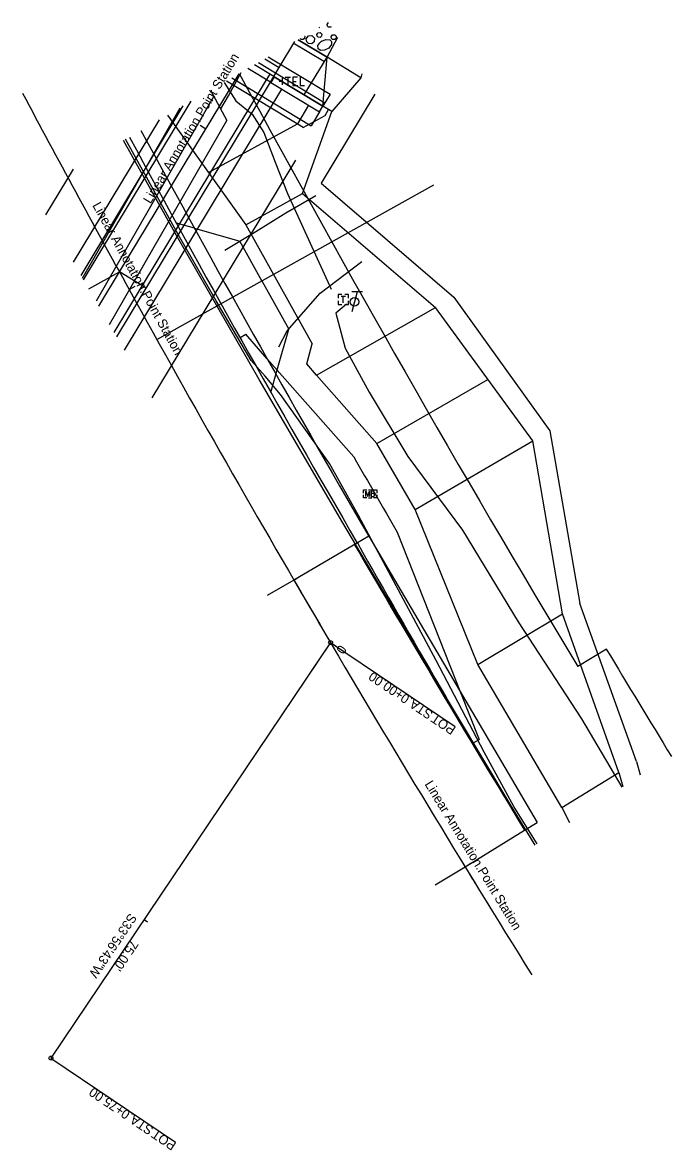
# Model space of a CAD drawing. Extents: x 2231639 to 2237084, y 681731 to 684172.
# Drawn here: x 2231639.3 to 2231736.5, y 683534.5 to 683703.4 of the extents above; entities that cross this region are included whole.
import ezdxf

# ---------------------------------------------------------------- set-up
doc = ezdxf.new("R2010")
doc.units = 0
for name, color, linetype in [('DR_P_Erosion_Control', 7, 'Continuous'), ('DR_P_Paved_Gutter', 7, 'Continuous'), ('DR_X_Storm_Sewer', 7, 'Continuous'), ('DT_P_Slope_Break_Line', 7, 'Continuous'), ('GE_P_Alignment', 7, 'Continuous'), ('GE_P_Alignment_100_Bearings', 7, 'Continuous'), ('GE_P_Alignment_100_Cardinal_Points', 7, 'Continuous'), ('GE_P_Alignment_100_Distances', 7, 'Continuous'), ('GE_P_Alignment_100_Stations', 7, 'Continuous'), ('GE_X_Alignment', 7, 'Continuous'), ('GE_X_Alignment_100_Stations', 7, 'Continuous'), ('HY_P_Water_Edge', 7, 'Continuous'), ('HY_X_Water_Edge', 7, 'Continuous'), ('PV_P_Drive', 7, 'Continuous'), ('PV_P_Field_Drive', 7, 'Continuous'), ('PV_X_Driveway', 7, 'Continuous'), ('PV_X_EOP', 7, 'Continuous'), ('PV_X_Shoulder_Aggregate', 7, 'Continuous'), ('RD_X_Cells', 7, 'Continuous'), ('RW_P_Const_Limits', 7, 'Continuous'), ('RW_X_Esmt_SH', 7, 'Continuous'), ('SH_Border', 7, 'Continuous'), ('SH_Cut_Line', 7, 'Continuous'), ('SH_Data', 7, 'Continuous'), ('SH_Masking', 7, 'Continuous'), ('SH_Named_Boundary', 7, 'Continuous'), ('UT_X_Telecom', 7, 'Continuous'), ('UT_X_Telecom_Cells', 7, 'Continuous')]:
    doc.layers.add(name, color=color, linetype=linetype)

msp = doc.modelspace()

# ---------------------------------------------------------------- linework, layer by layer
at = {"layer": 'DR_P_Erosion_Control'}
for p, q in [((2231684.92, 683703.08), (2231685.12, 683703.37)), ((2231684.91, 683698.17), (2231686.55, 683701.18))]:
    msp.add_line(p, q, dxfattribs=at)
for points in [[(2231683.37, 683701.57), (2231683.57, 683701.85), (2231683.9, 683701.87), (2231684.12, 683701.64), (2231684.09, 683701.31), (2231683.89, 683701.15), (2231683.57, 683701.17), (2231683.42, 683701.32), (2231683.37, 683701.57)], [(2231683.77, 683702.64), (2231683.7, 683702.58), (2231683.67, 683702.59)], [(2231685.53, 683702.74), (2231685.44, 683702.67), (2231685.12, 683702.69), (2231684.97, 683702.84), (2231684.92, 683703.08)], [(2231685.54, 683701.25), (2231685.74, 683701.53), (2231686.07, 683701.55), (2231686.29, 683701.32), (2231686.26, 683701), (2231686.06, 683700.83), (2231685.74, 683700.85), (2231685.59, 683701), (2231685.54, 683701.25)], [(2231681.53, 683701.35), (2231681.57, 683701.31), (2231681.54, 683700.98), (2231681.34, 683700.82), (2231681.02, 683700.84), (2231680.88, 683700.98)], [(2231681.78, 683700.91), (2231682.11, 683701.38), (2231682.65, 683701.41), (2231683.02, 683701.03), (2231682.97, 683700.49), (2231682.64, 683700.21), (2231682.11, 683700.25), (2231681.86, 683700.49), (2231681.78, 683700.91)], [(2231684.12, 683700.6), (2231684.75, 683700.85), (2231685.33, 683700.8), (2231685.6, 683700.54), (2231685.59, 683700.07), (2231685.17, 683699.54), (2231684.53, 683699.22), (2231683.92, 683699.21), (2231683.58, 683699.45), (2231683.55, 683699.93), (2231683.83, 683700.36), (2231684.14, 683700.62)]]:
    msp.add_lwpolyline(points, dxfattribs=at)
at = {"layer": 'DR_P_Paved_Gutter'}
for p, q in [((2231677.76, 683696.65), (2231680.1, 683700.52)), ((2231680.56, 683700.79), (2231684.91, 683698.17)), ((2231681.5, 683692.53), (2231684.91, 683698.17))]:
    msp.add_line(p, q, dxfattribs=at)
at = {"layer": 'DR_X_Storm_Sewer'}
for p, q in [((2231654.55, 683654.35), (2231678.13, 683693.4)), ((2231667.44, 683693.23), (2231669.89, 683688.72)), ((2231667.93, 683692.34), (2231650.31, 683661.64)), ((2231648.27, 683665.13), (2231662.91, 683690.62)), ((2231646.9, 683667.49), (2231659.79, 683688.82)), ((2231652.34, 683658.15), (2231669.89, 683688.72)), ((2231642.8, 683674.57), (2231646.93, 683681.41)), ((2231658.72, 683647.17), (2231680.24, 683682.79))]:
    msp.add_line(p, q, dxfattribs=at)
at = {"layer": 'DT_P_Slope_Break_Line'}
for p, q in [((2231684.91, 683698.17), (2231680.56, 683700.79)), ((2231684.28, 683690.85), (2231684.91, 683698.17)), ((2231689.95, 683695.12), (2231684.91, 683698.17)), ((2231684.28, 683690.85), (2231677.01, 683695.25)), ((2231689.95, 683695.12), (2231685.63, 683690.04)), ((2231690.12, 683695.67), (2231689.95, 683695.12)), ((2231682.15, 683690.98), (2231680.46, 683688.19)), ((2231681.25, 683677.78), (2231685.63, 683690.04)), ((2231685.63, 683690.04), (2231684.28, 683690.85)), ((2231661.02, 683689.53), (2231672.76, 683673.08)), ((2231667.17, 683680.91), (2231680.46, 683688.19)), ((2231672.76, 683673.08), (2231681.25, 683677.78)), ((2231681.25, 683677.78), (2231701.15, 683660.71)), ((2231672.76, 683673.08), (2231682.7, 683655.28)), ((2231683.35, 683650.6), (2231701.15, 683660.71)), ((2231715.72, 683640.76), (2231701.15, 683660.71)), ((2231681.86, 683652.29), (2231682.7, 683655.28)), ((2231683.35, 683650.6), (2231681.86, 683652.29)), ((2231692.39, 683640.33), (2231683.35, 683650.6)), ((2231692.39, 683640.33), (2231709, 683649.95)), ((2231698.09, 683630.49), (2231715.72, 683640.76)), ((2231720.2, 683614.85), (2231715.72, 683640.76)), ((2231698.09, 683630.49), (2231692.39, 683640.33)), ((2231707.51, 683607.27), (2231698.09, 683630.49)), ((2231707.51, 683607.27), (2231720.2, 683614.85)), ((2231728.61, 683591.1), (2231720.2, 683614.85)), ((2231720.08, 683585.88), (2231707.51, 683607.27)), ((2231720.08, 683585.88), (2231728.61, 683591.1)), ((2231728.61, 683591.1), (2231729.21, 683588.99)), ((2231720.08, 683585.88), (2231721.23, 683583.64))]:
    msp.add_line(p, q, dxfattribs=at)
at = {"layer": 'GE_P_Alignment'}
msp.add_line((2231685.43, 683610.56), (2231643.55, 683548.34), dxfattribs=at)
at = {"layer": 'GE_P_Alignment_100_Cardinal_Points'}
for p, q in [((2231685.43, 683610.56), (2231704.1, 683597.99)), ((2231685.43, 683610.56), (2231704.1, 683597.99)), ((2231643.55, 683548.34), (2231662.22, 683535.77))]:
    msp.add_line(p, q, dxfattribs=at)
for centre in [(2231685.43, 683610.56), (2231685.43, 683610.56), (2231643.55, 683548.34)]:
    msp.add_circle(centre, 0.3, dxfattribs=at)
at = {"layer": 'GE_P_Alignment_100_Stations'}
for p, q in [((2231666.74, 683687.43), (2231665.88, 683687.95)), ((2231685.43, 683610.56), (2231686.26, 683610)), ((2231685.43, 683610.56), (2231686.26, 683610)), ((2231657.51, 683569.08), (2231658.01, 683568.74))]:
    msp.add_line(p, q, dxfattribs=at)
at = {"layer": 'GE_X_Alignment'}
for start, end in [(208.09314, 208.94461), (208.94461, 211.97396)]:
    msp.add_arc((2233625.63, 684753.11), 2251.63, start, end, dxfattribs=at)
at = {"layer": 'GE_X_Alignment_100_Stations'}
for p, q in [((2231655.26, 683663.41), (2231656.14, 683663.89)), ((2231655.26, 683663.41), (2231656.14, 683663.89)), ((2231679.95, 683619.92), (2231680.46, 683620.23)), ((2231679.95, 683619.92), (2231680.46, 683620.23)), ((2231705.59, 683577), (2231706.44, 683577.52)), ((2231705.59, 683577), (2231706.44, 683577.52))]:
    msp.add_line(p, q, dxfattribs=at)
at = {"layer": 'HY_P_Water_Edge'}
for p, q in [((2231681.32, 683687.67), (2231669.83, 683694.61)), ((2231684.62, 683689.48), (2231685.14, 683690.34)), ((2231681.32, 683687.67), (2231684.62, 683689.48))]:
    msp.add_line(p, q, dxfattribs=at)
at = {"layer": 'HY_X_Water_Edge'}
msp.add_lwpolyline([(2231669.02, 683690.44), (2231670.14, 683692.42), (2231672.03, 683695.87)], dxfattribs=at)
at = {"layer": 'PV_P_Drive'}
for p, q in [((2231684.11, 683663.02), (2231684.11, 683663.01)), ((2231671.87, 683656.2), (2231672.74, 683656.7)), ((2231675.91, 683653.1), (2231672.74, 683656.7)), ((2231688.93, 683638.34), (2231675.91, 683653.1)), ((2231695.44, 683627.09), (2231704.91, 683603.1)), ((2231704.91, 683603.1), (2231707.69, 683596.05)), ((2231706.65, 683595.45), (2231707.69, 683596.05))]:
    msp.add_line(p, q, dxfattribs=at)
msp.add_arc((2233625.63, 684753.11), 2234.63, 209.92483, 210.25805, dxfattribs=at)
at = {"layer": 'PV_P_Field_Drive'}
for p, q in [((2231665.05, 683672.58), (2231662.33, 683673.36)), ((2231665.05, 683672.58), (2231671.82, 683670.64)), ((2231675.14, 683664.69), (2231671.82, 683670.64)), ((2231675.14, 683664.69), (2231679.16, 683657.48)), ((2231677.45, 683651.36), (2231679.16, 683657.48)), ((2231676.5, 683647.99), (2231677.45, 683651.36))]:
    msp.add_line(p, q, dxfattribs=at)
at = {"layer": 'PV_X_Driveway'}
for points in [[(2231669.61, 683669.29), (2231674.23, 683672.1), (2231678.73, 683674.88), (2231683.21, 683677.47)], [(2231677.7, 683654.83), (2231678.93, 683657.22), (2231683.89, 683662.84), (2231690.1, 683667.6)]]:
    msp.add_lwpolyline(points, dxfattribs=at)
at = {"layer": 'PV_X_EOP'}
msp.add_lwpolyline([(2231716.1, 683580.2), (2231712.66, 683585.86), (2231699.92, 683607.11), (2231687.29, 683628.5), (2231674.72, 683649.94), (2231662.34, 683671.5), (2231654.39, 683685.71)], dxfattribs=at)
at = {"layer": 'PV_X_Shoulder_Aggregate'}
msp.add_lwpolyline([(2231716.39, 683580.4), (2231712.91, 683586.03), (2231708.44, 683594.13), (2231701.28, 683607.87), (2231689.62, 683629.59), (2231685.28, 683637.38), (2231677.96, 683647.67), (2231675.66, 683650.41), (2231673.54, 683652.78), (2231668.3, 683661.73), (2231662.61, 683671.65), (2231654.69, 683685.89)], dxfattribs=at)
at = {"layer": 'RD_X_Cells'}
for p, q in [((2231691.11, 683633.43), (2231691.61, 683633.43)), ((2231691.11, 683632.21), (2231691.61, 683632.21)), ((2231691.36, 683632.82), (2231691.36, 683632.82))]:
    msp.add_line(p, q, dxfattribs=at)
for points in [[(2231690.36, 683632.94), (2231690.36, 683633.43), (2231690.85, 683633.43)], [(2231690.85, 683632.21), (2231690.36, 683632.21), (2231690.36, 683632.69)], [(2231690.72, 683632.42), (2231690.72, 683633.22), (2231691.01, 683632.42), (2231691.28, 683633.22), (2231691.28, 683632.42)], [(2231691.87, 683632.85), (2231691.91, 683632.88), (2231691.93, 683632.9), (2231691.94, 683632.92), (2231691.94, 683632.93), (2231691.96, 683632.96), (2231691.96, 683632.98), (2231691.98, 683633.02), (2231691.98, 683633.04), (2231691.98, 683633.07), (2231691.97, 683633.1), (2231691.96, 683633.14), (2231691.94, 683633.16), (2231691.91, 683633.19), (2231691.88, 683633.2), (2231691.87, 683633.21), (2231691.84, 683633.22), (2231691.53, 683633.22), (2231691.53, 683632.42), (2231691.87, 683632.42), (2231691.92, 683632.44), (2231691.96, 683632.47), (2231691.99, 683632.53), (2231692.01, 683632.58), (2231692.01, 683632.64), (2231692.01, 683632.68), (2231692, 683632.71), (2231691.98, 683632.77), (2231691.94, 683632.81), (2231691.87, 683632.85), (2231691.53, 683632.85)], [(2231691.87, 683633.43), (2231692.36, 683633.43), (2231692.36, 683632.94)], [(2231692.36, 683632.69), (2231692.36, 683632.21), (2231691.87, 683632.21)]]:
    msp.add_lwpolyline(points, dxfattribs=at)
at = {"layer": 'RW_P_Const_Limits'}
for p, q in [((2231692.07, 683692.67), (2231684.05, 683679.33)), ((2231684.05, 683679.33), (2231703.92, 683662.28)), ((2231703.92, 683662.28), (2231718.31, 683642.27)), ((2231718.31, 683642.27), (2231722.78, 683616.39)), ((2231731.27, 683592.73), (2231722.78, 683616.39)), ((2231731.27, 683592.73), (2231731.82, 683590.74))]:
    msp.add_line(p, q, dxfattribs=at)
at = {"layer": 'RW_X_Esmt_SH'}
msp.add_line((2231726.76, 683609.57), (2231722.47, 683606.99), dxfattribs=at)
for radius, start, end in [(2221.63, 208.42121, 211.05725), (2216.63, 211.05725, 211.54264)]:
    msp.add_arc((2233625.63, 684753.11), radius, start, end, dxfattribs=at)
at = {"layer": 'SH_Border'}
for p, q in [((2231653.02, 683656.98), (2231675.85, 683694.78)), ((2231675.85, 683694.78), (2231676.37, 683695.64)), ((2231676.42, 683694.43), (2231676.94, 683695.29)), ((2231653.4, 683656.32), (2231676.42, 683694.43)), ((2231648.43, 683664.86), (2231664.57, 683691.58)), ((2231648.05, 683665.52), (2231663.37, 683690.89))]:
    msp.add_line(p, q, dxfattribs=at)
at = {"layer": 'SH_Cut_Line'}
for p, q in [((2231649.22, 683663.5), (2231653.81, 683666.03)), ((2231657.81, 683663.62), (2231653.81, 683666.03)), ((2231691.18, 683626.47), (2231689.45, 683625.46)), ((2231691.18, 683626.47), (2231716.37, 683583.6)), ((2231714.49, 683582.45), (2231716.37, 683583.6))]:
    msp.add_line(p, q, dxfattribs=at)
msp.add_arc((2233625.63, 684753.11), 2238.63, 208.43282, 210.21693, dxfattribs=at)
at = {"layer": 'SH_Data'}
for p, q in [((2231677.01, 683695.25), (2231676.94, 683695.29)), ((2231676.49, 683694.39), (2231676.42, 683694.43))]:
    msp.add_line(p, q, dxfattribs=at)
msp.add_lwpolyline([(2231676.42, 683694.43), (2231676.94, 683695.29), (2231677.01, 683695.25), (2231676.49, 683694.39)], close=True, dxfattribs=at)
at = {"layer": 'SH_Masking'}
for p, q in [((2231679.82, 683700.36), (2231684.52, 683697.53)), ((2231676.11, 683698.23), (2231685.36, 683692.64)), ((2231676.42, 683694.43), (2231673.06, 683696.47)), ((2231676.94, 683695.29), (2231674.05, 683697.04)), ((2231674.62, 683697.37), (2231684.59, 683691.35)), ((2231675.61, 683697.94), (2231677.76, 683696.65)), ((2231676.94, 683695.29), (2231677.76, 683696.65)), ((2231670.66, 683695.09), (2231675.17, 683692.37)), ((2231676.49, 683694.39), (2231677.01, 683695.25)), ((2231677.01, 683695.25), (2231684.28, 683690.85)), ((2231676.49, 683694.39), (2231683.77, 683690)), ((2231675.17, 683692.37), (2231682.52, 683687.93)), ((2231685.36, 683692.64), (2231684.28, 683690.85)), ((2231683.77, 683690), (2231682.52, 683687.93)), ((2231683.77, 683690), (2231684.28, 683690.85))]:
    msp.add_line(p, q, dxfattribs=at)
at = {"layer": 'SH_Named_Boundary'}
for p, q in [((2231653.81, 683666.03), (2231671.74, 683695.71)), ((2231659.42, 683655.92), (2231700.9, 683679.06)), ((2231650.72, 683660.92), (2231653.81, 683666.03)), ((2231689.45, 683625.46), (2231679.95, 683619.92)), ((2231679.95, 683619.92), (2231675.93, 683617.59)), ((2231685.43, 683610.56), (2231682.53, 683606.25)), ((2231705.59, 683577), (2231714.49, 683582.45)), ((2231701.13, 683574.27), (2231705.59, 683577))]:
    msp.add_line(p, q, dxfattribs=at)
for centre, radius, start, end in [((2233625.63, 684753.11), 2240.63, 208.43418, 210.21693), ((2233616.92, 684719.02), 2216.08, 209.56858, 210.85524), ((2234515.94, 685281.36), 3276.33, 210.36396, 211.23427), ((2233625.63, 684753.11), 2251.63, 210.21693, 210.49316), ((2233625.63, 684753.11), 2251.63, 211.48925, 211.57072)]:
    msp.add_arc(centre, radius, start, end, dxfattribs=at)
at = {"layer": 'UT_X_Telecom'}
for points in [[(2231669.49, 683694.41), (2231671.24, 683691.66), (2231673.71, 683689.65), (2231675.44, 683686.93), (2231677.16, 683682.48), (2231678.97, 683677.79), (2231685.55, 683663.46)], [(2231687.84, 683661.21), (2231686.22, 683659.85), (2231687.63, 683654.63), (2231691.22, 683648.05), (2231696.99, 683638.42), (2231705.2, 683627.4), (2231713.56, 683613.68), (2231723.03, 683599.16), (2231729.1, 683588.92)]]:
    msp.add_lwpolyline(points, dxfattribs=at)
at = {"layer": 'UT_X_Telecom_Cells'}
for p, q in [((2231678.22, 683694.07), (2231678.22, 683695.07)), ((2231678.22, 683694.57), (2231677.72, 683694.57)), ((2231690.21, 683663.06), (2231688.61, 683663.06)), ((2231689.41, 683663.06), (2231688.61, 683660.06)), ((2231687.02, 683662.43), (2231687.67, 683662.43)), ((2231687.35, 683661.43), (2231687.35, 683662.43)), ((2231687.35, 683661.93), (2231687.35, 683661.93))]:
    msp.add_line(p, q, dxfattribs=at)
for points in [[(2231678.63, 683695.19), (2231679.41, 683695.19)], [(2231679.02, 683695.19), (2231679.02, 683693.94)], [(2231680.48, 683695.19), (2231679.8, 683695.19), (2231679.8, 683693.94), (2231680.53, 683693.94)], [(2231680.87, 683695.19), (2231680.87, 683693.94), (2231681.55, 683693.94)], [(2231679.8, 683694.57), (2231680.28, 683694.57)], [(2231687.15, 683662.68), (2231686.6, 683662.68), (2231686.6, 683662.13)], [(2231688.1, 683662.13), (2231688.1, 683662.68), (2231687.55, 683662.68)], [(2231686.6, 683661.73), (2231686.6, 683661.18), (2231687.15, 683661.18)], [(2231687.55, 683661.18), (2231688.1, 683661.18), (2231688.1, 683661.73)]]:
    msp.add_lwpolyline(points, dxfattribs=at)
msp.add_circle((2231689.01, 683661.56), 0.65, dxfattribs=at)

# ---------------------------------------------------------------- texts
at = {"layer": 'GE_P_Alignment_100_Bearings'}
msp.add_text('S33°56\'43"W', height=1.4, rotation=236.0548, dxfattribs=at).set_placement((2231655.34, 683570.14))
at = {"layer": 'GE_P_Alignment_100_Cardinal_Points'}
for s, p in [('0+00.00', (2231697.41, 683602.47)), ('0+00.00', (2231697.41, 683602.47)), (' STA. ', (2231701.33, 683599.83)), (' STA. ', (2231701.33, 683599.83)), ('POT', (2231704.32, 683597.82)), ('POT', (2231704.32, 683597.82)), ('0+75.00', (2231655.53, 683540.25)), (' STA. ', (2231659.45, 683537.61)), ('POT', (2231662.44, 683535.6))]:
    msp.add_text(s, height=1.4, rotation=146.0548, dxfattribs=at).set_placement(p)
at = {"layer": 'GE_P_Alignment_100_Distances'}
msp.add_text("75.00'", height=1.4, rotation=236.0548, dxfattribs=at).set_placement((2231655.58, 683566.17))
at = {"layer": 'GE_P_Alignment_100_Stations'}
for s, rotation, p in [('Linear Annotation.Point Station', 58.8683, (2231658.46, 683676.14)), ('0', 236.0548, (2231686.78, 683610.32)), ('0', 236.0548, (2231686.78, 683610.32))]:
    msp.add_text(s, height=1.4, rotation=rotation, dxfattribs=at).set_placement(p)
at = {"layer": 'GE_X_Alignment_100_Stations'}
for rotation, p in [(298.9446, (2231649.71, 683676.02)), (298.9446, (2231649.71, 683676.02)), (301.4893, (2231699.48, 683589.36))]:
    msp.add_text('Linear Annotation.Point Station', height=1.4, rotation=rotation, dxfattribs=at).set_placement(p)

doc.saveas('drawing.dxf')
